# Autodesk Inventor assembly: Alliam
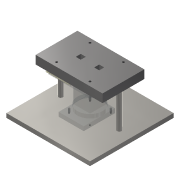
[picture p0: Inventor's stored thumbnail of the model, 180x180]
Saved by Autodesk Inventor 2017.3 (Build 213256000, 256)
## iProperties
Part Number: Alliam
Material: 一般
Document SubType Name: Assembly
Designer: kyushu-hep
Author: kyushu-hep
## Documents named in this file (8)
- C:\Users\kyushu-hep\Desktop\dkobayas\FlexAssembly3\Alliam.iam
- C:\Users\kyushu-hep\Desktop\dkobayas\FlexAssembly3\FlexBase.ipt
- C:\Users\kyushu-hep\Desktop\dkobayas\FlexAssembly3\ModuleBase.ipt
- C:\Users\kyushu-hep\Desktop\dkobayas\FlexAssembly3\Module.ipt
- C:\Users\kyushu-hep\Desktop\dkobayas\FlexAssembly3\FPC2.ipt
- C:\Users\kyushu-hep\Desktop\dkobayas\FlexAssembly3\base1.ipt
- C:\Users\kyushu-hep\Desktop\dkobayas\FlexAssembly3\ClearBoard.ipt
- C:\Users\kyushu-hep\Desktop\dkobayas\FlexAssembly3\Stages.ipt
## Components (7 placed, 7 different names)
1. FlexBase:1 — メイト:18, メイト:19, メイト:20, メイト:21, メイト:22, メイト:24, メイト:25
2. base1:1 — メイト:13, メイト:14, メイト:24, メイト:25, メイト:26, メイト:27, メイト:28
3. FPC2:1 — メイト:21, メイト:22, メイト:23
4. ModuleBase:1 — メイト:15, メイト:16, メイト:17, メイト:29, メイト:30, メイト:31
5. Module:1 — メイト:15, メイト:16, メイト:17
6. ClearBoard:1 — メイト:18, メイト:19, メイト:20, メイト:23
7. Stages:1 — メイト:26, メイト:27, メイト:28, メイト:29, メイト:30, メイト:31
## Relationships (19: Mate 19)
- メイト:13 [Mate]: base1:1
- メイト:14 [Mate]: base1:1
- メイト:15 [Mate]: ModuleBase:1 ↔ Module:1
- メイト:16 [Mate]: ModuleBase:1 ↔ Module:1
- メイト:17 [Mate]: ModuleBase:1 ↔ Module:1
- メイト:18 [Mate]: FlexBase:1 ↔ ClearBoard:1
- メイト:19 [Mate]: FlexBase:1 ↔ ClearBoard:1
- メイト:20 [Mate]: FlexBase:1 ↔ ClearBoard:1
- メイト:21 [Mate]: FlexBase:1 ↔ FPC2:1
- メイト:22 [Mate]: FlexBase:1 ↔ FPC2:1
- メイト:23 [Mate]: FPC2:1 ↔ ClearBoard:1
- メイト:24 [Mate]: FlexBase:1 ↔ base1:1
- メイト:25 [Mate]: FlexBase:1 ↔ base1:1
- メイト:26 [Mate]: base1:1 ↔ Stages:1
- メイト:27 [Mate]: base1:1 ↔ Stages:1
- メイト:28 [Mate]: base1:1 ↔ Stages:1
- メイト:29 [Mate]: ModuleBase:1 ↔ Stages:1
- メイト:30 [Mate]: ModuleBase:1 ↔ Stages:1
- メイト:31 [Mate]: ModuleBase:1 ↔ Stages:1
